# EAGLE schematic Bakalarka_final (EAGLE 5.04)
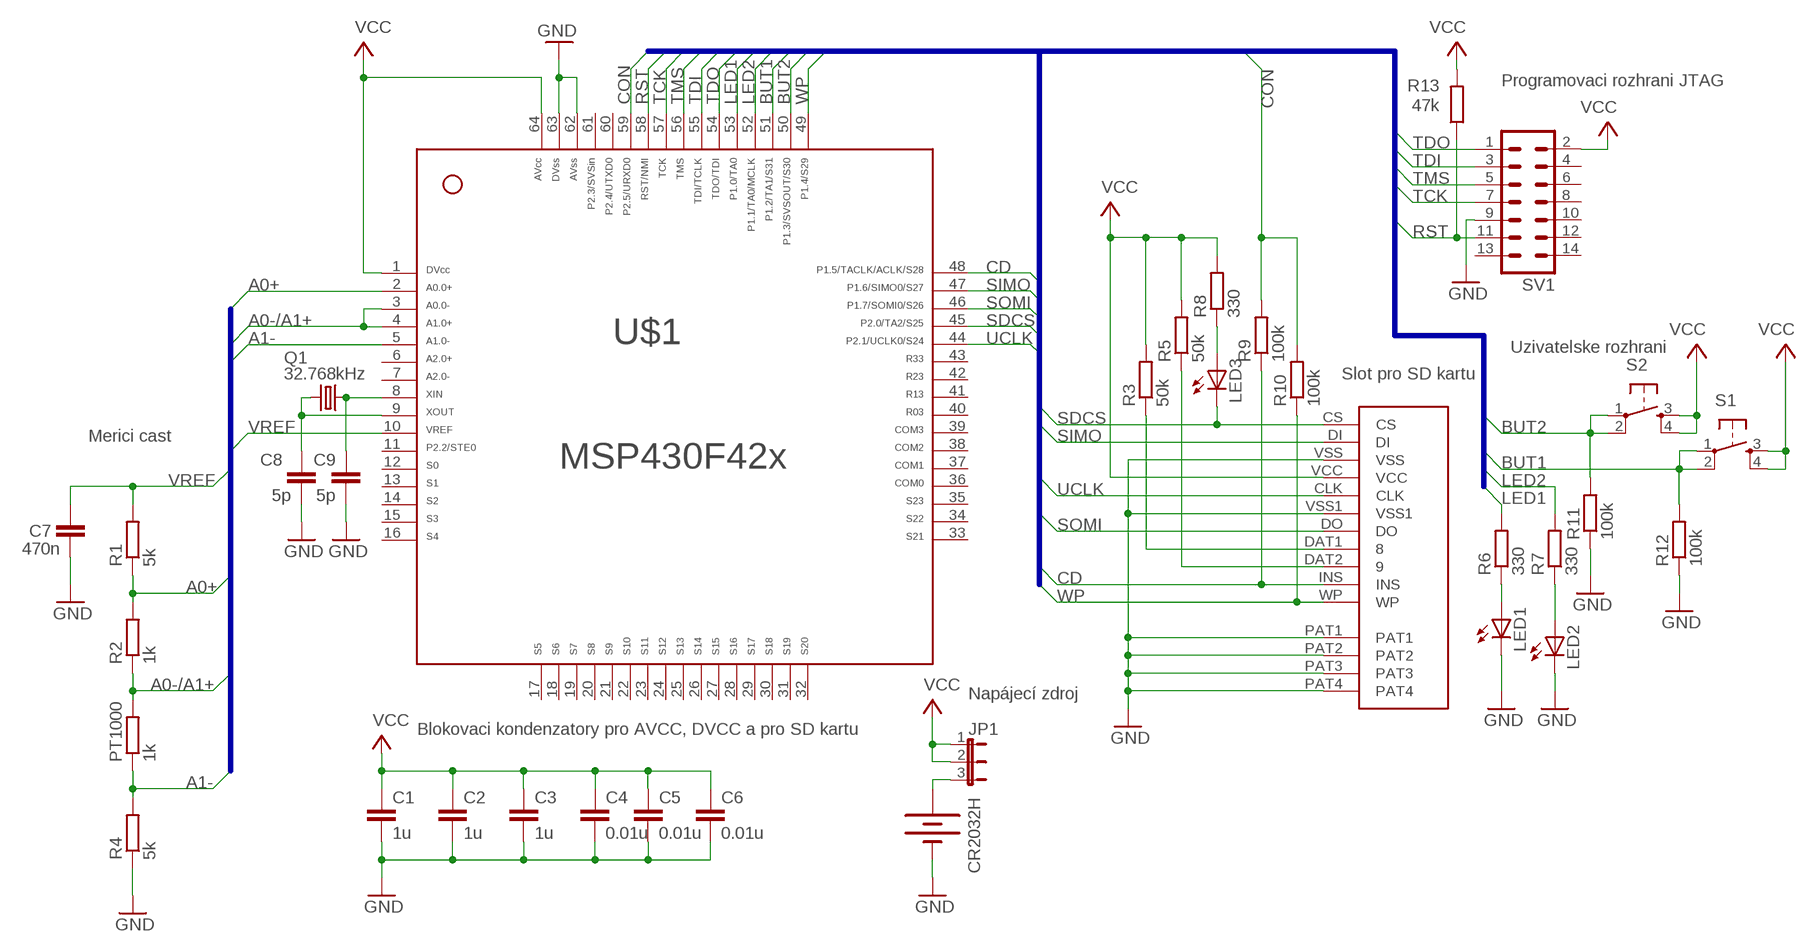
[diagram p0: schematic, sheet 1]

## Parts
C1  1u  C-EUC1206  [C1206]
C2  1u  C-EUC1206  [C1206]
C3  1u  C-EUC1206  [C1206]
C4  0.01u  C-EUC1206  [C1206]
C5  0.01u  C-EUC1206  [C1206]
C6  0.01u  C-EUC1206  [C1206]
C7  470n  C-EUC1206  [C1206]
C8  5p  C-EUC1206  [C1206]
C9  5p  C-EUC1206  [C1206]
CR2032H  BATTERY20PTH  [BATTCOM_20MM_PTH]
JP1  JUMPER-3PTH  [1X03]
LED1  LED3MM  [LED3MM]
LED2  LED3MM  [LED3MM]
LED3  LED3MM  [LED3MM]
PT1000  1k  R-EU_R1206  [R1206]
Q1  32.768kHz  CRYSTALTC38H  [TC38H]
R1  5k  R-EU_R1206  [R1206]
R2  1k  R-EU_R1206  [R1206]
R3  50k  R-EU_R1206  [R1206]
R4  5k  R-EU_R1206  [R1206]
R5  50k  R-EU_R1206  [R1206]
R6  330  R-EU_R1206  [R1206]
R7  330  R-EU_R1206  [R1206]
R8  330  R-EU_R1206  [R1206]
R9  100k  R-EU_R1206  [R1206]
R10  100k  R-EU_R1206  [R1206]
R11  100k  R-EU_R1206  [R1206]
R12  100k  R-EU_R1206  [R1206]
R13  47k  R-EU_R1206  [R1206]
S1  TAC_SWITCHPTH  [TACTILE-PTH]
S2  TAC_SWITCHPTH  [TACTILE-PTH]
SV1  MA07-2  [MA07-2]
U$1  F42X---PM64  [PM/PAG64]
U$3  SDSOCKET1  [SDSOCKET1]

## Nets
A0+: R1.1 R2.2 U$1.2
A0-/A1+: PT1000.2 R2.1 U$1.3 U$1.4
A1-: PT1000.1 R4.2 U$1.5
BUT1: R12.2 S1.1 S1.2 U$1.51
BUT2: R11.2 S2.1 S2.2 U$1.50
CD: R9.1 U$1.48 U$3.INS
CON: R9.2 R10.2 U$1.59
GND: C1.2 C2.2 C3.2 C4.2 C5.2 C6.2 C7.2 C8.2 C9.2 CR2032H.2(-) LED1.K(C) LED2.K(C) R4.1 R11.1 R12.1 SV1.9 U$1.62 U$1.63 U$3.PAT1 U$3.PAT2 U$3.PAT3 U$3.PAT4 U$3.VSS U$3.VSS1
LED1: R6.2 U$1.53
LED2: R7.2 U$1.52
N$1: C9.1 Q1.1 U$1.8
N$2: C8.1 Q1.2 U$1.9
N$3: CR2032H.1(+) JP1.3
N$4: R3.1 U$3.DAT1
N$5: R5.1 U$3.DAT2
N$6: LED1.A R6.1
N$7: LED2.A R7.1
N$8: LED3.A R8.1
RST: R13.1 SV1.11 U$1.58
SDCS: LED3.K(C) U$1.45 U$3.CS
SIMO: U$1.47 U$3.DI
SOMI: U$1.46 U$3.DO
TCK: SV1.7 U$1.57
TDI: SV1.3 U$1.55
TDO: SV1.1 U$1.54
TMS: SV1.5 U$1.56
UCLK: U$1.44 U$3.CLK
V+: C1.1 C2.1 C3.1 C4.1 C5.1 C6.1 JP1.1 JP1.2 R3.2 R5.2 R8.2 R13.2 S1.3 S1.4 S2.3 S2.4 SV1.2 U$1.1 U$1.64 U$3.VCC ; supply symbol labelled VCC
VREF: C7.1 R1.2 U$1.10
WP: R10.1 U$1.49 U$3.WP
Unconnected: SV1.4 SV1.6 SV1.8 SV1.10 SV1.12 SV1.13 SV1.14 U$1.6 U$1.7 U$1.11 U$1.12 U$1.13 U$1.14 U$1.15 U$1.16 U$1.17 U$1.18 U$1.19 U$1.20 U$1.21 U$1.22 U$1.23 U$1.24 U$1.25 U$1.26 U$1.27 U$1.28 U$1.29 U$1.30 U$1.31 U$1.32 U$1.33 U$1.34 U$1.35 U$1.36 U$1.37 U$1.38 U$1.39 U$1.40 U$1.41 U$1.42 U$1.43 U$1.60 U$1.61

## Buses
SOMI,SIMO,UCLK,SDCS,CD,WP,TDO,TDI,TMS,TCK,RST,LED1,LED2,BUT1,BUT2,CON
VREF,A0+,A0-/A1+,A1-

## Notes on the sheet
- Programovaci rozhrani JTAG
- Uzivatelske rozhrani
- Slot pro SD kartu
- Merici cast
- Napájecí zdroj
- Blokovaci kondenzatory pro AVCC, DVCC a pro SD kartu

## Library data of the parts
C1-C9 = rcl:C-EU: CAPACITOR, European symbol
CR2032H = SparkFun:BATTERY: Battery Holders
JP1 = SparkFun:JUMPER-3
LED1-LED3 = led:LED: LED
PT1000 R1-R13 = rcl:R-EU_: RESISTOR, European symbol
Q1 = crystal:CRYSTAL: CRYSTAL
S1 S2 = SparkFun:TAC_SWITCH: Momentary Switch Button commonly used for reset or general input. Spark Fun Electronics SKU : COM-00097
SV1 = con-lstb:MA07-2: PIN HEADER
U$1 = TI_MSP430_v13:F42X---PM64: *** MSP430F42x *** PM64
U$3 = SDSOCKET:SDSOCKET1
